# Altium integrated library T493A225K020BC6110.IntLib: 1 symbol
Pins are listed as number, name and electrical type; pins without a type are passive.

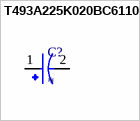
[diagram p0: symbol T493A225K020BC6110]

## T493A225K020BC6110
designator C?
Solid Tantalum Electrolytic Capacitor; MF: Kemet; MP: T493A225K020BC6110
footprint CAPMP3216X180N
pins: 1, 2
